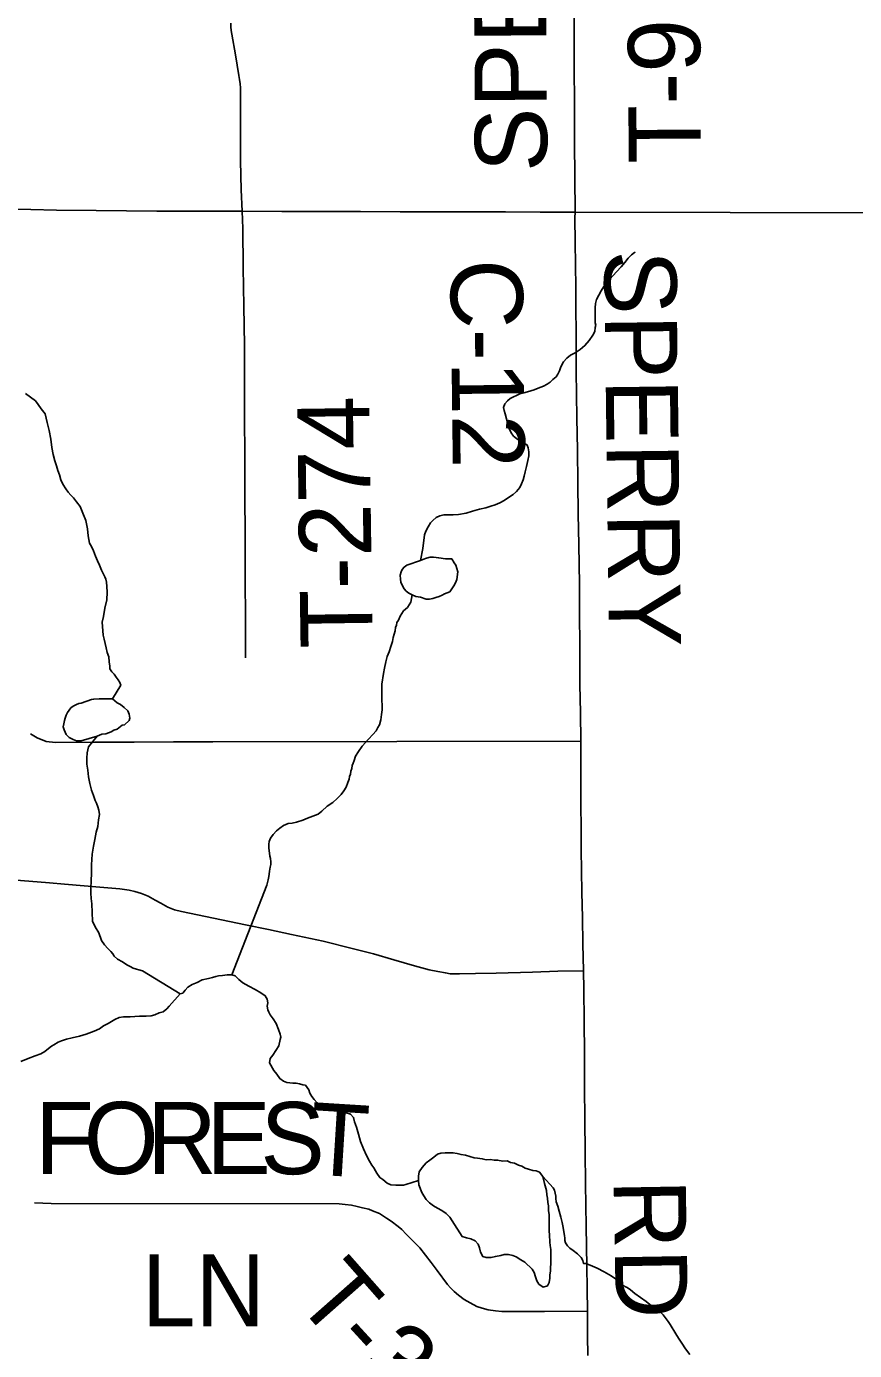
# Model space of a CAD drawing. Extents: x 103424 to 290657, y 38711 to 110967.
# Drawn here: x 112838 to 116302, y 74147 to 79687 of the extents above; entities that cross this region are included whole.
import ezdxf

# ---------------------------------------------------------------- set-up
doc = ezdxf.new("R2010")
doc.units = 0
for name, color, linetype in [('GM_X_County_Road', 7, 'Continuous'), ('GM_X_County_Road_Text', 7, 'Continuous'), ('GM_X_Minor_Lake', 7, 'Continuous'), ('GM_X_Minor_River', 7, 'Continuous'), ('GM_X_Township_Road', 7, 'Continuous'), ('GM_X_Township_Road_Text', 7, 'Continuous'), ('GM_X_US_Route', 7, 'Continuous'), ('SC_Scratch1', 7, 'Continuous')]:
    doc.layers.add(name, color=color, linetype=linetype)

msp = doc.modelspace()

# ---------------------------------------------------------------- linework, layer by layer
at = {"layer": 'GM_X_County_Road'}
for points in [[(115157.3, 76697.4), (115155.4, 76815.4), (115153.6, 76933.4), (115152.7, 77098.5), (115152.1, 77226), (115151.4, 77353.6), (115148.7, 77518.6), (115146.5, 77648.3), (115144.4, 77777.9), (115142.7, 77913.7), (115141.1, 78049.5), (115139.5, 78147.3), (115138, 78245.1), (115137.1, 78410.1), (115136.5, 78502.6), (115136, 78595.1), (115134.6, 78689.5), (115133.2, 78784), (115132.1, 78886), (115132.9, 78910)], [(115168.7, 75736), (115165.6, 75849.2), (115163.8, 75957.1), (115162, 76065.1), (115160.5, 76154.4), (115158.9, 76243.6), (115157.7, 76520.2), (115157, 76603.8), (115157.3, 76697.4)], [(115184.4, 74311.6), (115183.3, 74406.2), (115182.2, 74500.8), (115179.3, 74665.8), (115177.8, 74755.6), (115176.2, 74845.4), (115175.3, 74978.4), (115174.3, 75111.4), (115173.2, 75250.6), (115172.1, 75389.9), (115170.6, 75524.7), (115169.2, 75659.5), (115168.7, 75736)], [(115186.6, 74126.7), (115184.9, 74209.2), (115184.4, 74311.6)]]:
    msp.add_lwpolyline(points, dxfattribs=at)
at = {"layer": 'GM_X_Minor_Lake'}
for points in [[(114486.6, 77452.7), (114495.9, 77456.3), (114512, 77462.6), (114526.1, 77466.7), (114540.2, 77466.9), (114562.5, 77463.1), (114590.8, 77459.3), (114617.1, 77459.6), (114627.3, 77443.5), (114633.5, 77433.5), (114641.9, 77405.3), (114638.3, 77372.9), (114632.4, 77358.7), (114626.4, 77346.5), (114608.6, 77322.1), (114586.5, 77313.8), (114576.4, 77307.7), (114564.4, 77301.5), (114550.3, 77297.3), (114538.2, 77293.1), (114524.1, 77291), (114510, 77290.8), (114485.6, 77298.7), (114467.4, 77302.5), (114451.2, 77308.4), (114437, 77316.4), (114426.8, 77324.4), (114418.6, 77334.4), (114412.4, 77344.4), (114404.1, 77362.5), (114402, 77374.6), (114401.8, 77390.8), (114405.7, 77404.9), (114409.6, 77415.1), (114417.5, 77425.3), (114429.6, 77433.5), (114486.6, 77452.7)], [(114486.6, 77452.7), (114429.6, 77433.5), (114417.5, 77425.3), (114409.6, 77415.1), (114405.7, 77404.9), (114401.8, 77390.8), (114402, 77374.6), (114404.1, 77362.5), (114412.4, 77344.4), (114418.6, 77334.4), (114426.8, 77324.4), (114437, 77316.4), (114451.2, 77308.4), (114467.4, 77302.5), (114485.6, 77298.7), (114510, 77290.8), (114524.1, 77291), (114538.2, 77293.1), (114550.3, 77297.3)], [(114550.3, 77297.3), (114564.4, 77301.5), (114576.4, 77307.7), (114586.5, 77313.8), (114608.6, 77322.1), (114626.4, 77346.5), (114632.4, 77358.7), (114638.3, 77372.9), (114641.9, 77405.3), (114633.5, 77433.5), (114627.3, 77443.5), (114617.1, 77459.6), (114590.8, 77459.3), (114562.5, 77463.1), (114540.2, 77466.9), (114526.1, 77466.7), (114512, 77462.6), (114495.9, 77456.3), (114486.6, 77452.7)], [(113110, 76871), (113067, 76856.3), (113056.9, 76854.1), (113046.9, 76850), (113032.8, 76843.8), (113022.8, 76835.6), (113008.9, 76817.3), (113003, 76805.1), (112999.1, 76793), (112997.2, 76782.8), (112993.3, 76768.7), (112991.4, 76756.5), (112995.6, 76744.4), (113003.9, 76724.3), (113016.2, 76712.3), (113032.4, 76704.4), (113046.6, 76698.5), (113066.8, 76698.7), (113133.3, 76717.5), (113143.3, 76721.7), (113153.4, 76725.8), (113169.5, 76728), (113191.6, 76736.3), (113203.7, 76742.5), (113217.7, 76746.7), (113237.7, 76763), (113247.8, 76765.1), (113267.8, 76783.5), (113269.7, 76793.6), (113267.5, 76809.8), (113261.3, 76823.9), (113247, 76837.9), (113230.7, 76849.8), (113216.4, 76857.8), (113198.1, 76873.7), (113191.8, 76873.7)], [(113191.8, 76873.7), (113184, 76873.6), (113161.7, 76873.4), (113141.5, 76873.2), (113119.3, 76872.9), (113110, 76871)], [(114895.8, 74922.6), (114879.7, 74930.6), (114863.5, 74934.5), (114849.4, 74940.4), (114831.3, 74940.3), (114809.1, 74944.2), (114795.1, 74944.1), (114778.9, 74946), (114760.8, 74945.9), (114744.7, 74949.8), (114724.6, 74951.7), (114710.5, 74953.6), (114674.2, 74965.4), (114656, 74967.3), (114639.9, 74971.2), (114621.8, 74975.1), (114589.6, 74974.9), (114571.5, 74972.8), (114557.4, 74968.7), (114541.4, 74956.5), (114525.4, 74944.2), (114509.4, 74932), (114493.4, 74913.8), (114481.4, 74895.6), (114477.5, 74877.4), (114477.6, 74859.2), (114479.8, 74841.1), (114492.1, 74808.9), (114500.2, 74794.9), (114510.4, 74778.8), (114524.6, 74764.8), (114540.8, 74752.8), (114556.9, 74742.8), (114575.1, 74732.9), (114593.3, 74720.9), (114609.5, 74704.9), (114618.2, 74689.5)], [(115005.6, 74846.6), (114998.8, 74874.9), (114984.6, 74893), (114970.5, 74898.9), (114956.4, 74900.8), (114938.2, 74906.8), (114924.1, 74910.7), (114909.9, 74918.6), (114895.8, 74922.6)], [(114618.2, 74689.5), (114660.4, 74624.6), (114678.5, 74618.7), (114696.7, 74614.8), (114714.8, 74606.8), (114727, 74592.8), (114733.2, 74576.7), (114737.3, 74558.6), (114747.5, 74540.5), (114761.6, 74536.6), (114781.7, 74536.7), (114799.8, 74540.9), (114821.9, 74545.1), (114836, 74549.2), (114854.1, 74549.3), (114872.2, 74545.4), (114886.4, 74539.4), (114906.6, 74527.5), (114922.8, 74517.5), (114953.1, 74487.5), (114961.3, 74473.4), (114967.5, 74455.3), (114973.6, 74439.2), (114981.7, 74425.2), (114999.9, 74413.2), (115018, 74417.4), (115024, 74431.5), (115027.9, 74449.7), (115027.8, 74463.8), (115029.7, 74479.9), (115029.6, 74494.1), (115031.5, 74510.2), (115031.1, 74570.7), (115028.9, 74586.8), (115026.8, 74600.9), (115026.6, 74631.1), (115024.5, 74647.2), (115024, 74715.8), (115021.9, 74733.9), (115021.8, 74752.1), (115019.7, 74766.2), (115017.5, 74784.3), (115015.4, 74798.4), (115013.3, 74816.5), (115005.6, 74846.6)]]:
    msp.add_lwpolyline(points, dxfattribs=at)
at = {"layer": 'GM_X_Minor_River'}
for points in [[(114566.5, 77638.8), (114584.6, 77643.1), (114604.8, 77643.3), (114623, 77643.4), (114645.2, 77645.7), (114677.4, 77650.1), (114703.6, 77658.4), (114733.8, 77666.8), (114760, 77673.1), (114780.1, 77679.4), (114798.2, 77685.6), (114818.3, 77693.9), (114836.4, 77704.2), (114854.4, 77716.5), (114874.5, 77728.8), (114888.4, 77741), (114902.4, 77757.3), (114908.3, 77773.6), (114916.2, 77789.8), (114920, 77806), (114923.8, 77824.2), (114929.6, 77846.5), (114935.4, 77870.8), (114939.2, 77891), (114939, 77907.2), (114936.8, 77923.3), (114932.6, 77935.4), (114914.3, 77947.3), (114902.1, 77953.3), (114887.9, 77963.2), (114875.7, 77973.2), (114865.4, 77987.3), (114857.1, 78005.3), (114850.8, 78025.5), (114846.5, 78045.6), (114840.2, 78065.8), (114836, 78079.9), (114833.9, 78092), (114839.8, 78108.2), (114849.7, 78120.4), (114861.7, 78130.6), (114901.9, 78149.2), (114918, 78153.4), (114934.1, 78157.6), (114948.2, 78161.8), (114962.3, 78166), (114978.3, 78174.2), (115000.4, 78182.5), (115016.5, 78190.8), (115028.5, 78199), (115040.5, 78209.2), (115054.5, 78221.4), (115060.5, 78231.6), (115068.4, 78245.8), (115072.3, 78258), (115076.2, 78268.1), (115084.1, 78284.4), (115098.1, 78298.6), (115114.1, 78310.9), (115134.1, 78321.2), (115154.2, 78335.6), (115174.2, 78351.9), (115192.1, 78372.3), (115208, 78394.7), (115215.9, 78410.9), (115217.7, 78427.1), (115219.6, 78437.2), (115217.5, 78447.3), (115217.3, 78465.5), (115217.1, 78483.6), (115216.9, 78499.8), (115216.8, 78509.9), (115218.6, 78528.1), (115222.4, 78544.3), (115232.3, 78562.6), (115242.2, 78580.9), (115258.1, 78605.2), (115278, 78629.7), (115305.9, 78660.3), (115325.9, 78680.7), (115341.8, 78699), (115355.7, 78717.3), (115369.7, 78731.6), (115381.7, 78741.8), (115383.7, 78741.8), (115381.7, 78741.8)], [(113198.1, 76873.7), (113231.8, 76930.6), (113227.6, 76942.7), (113221.4, 76952.7), (113213.2, 76964.8), (113205, 76976.8), (113194.8, 76986.8), (113186.5, 76998.8), (113186.4, 77011), (113184.2, 77029.1), (113181.9, 77049.3), (113175.6, 77067.4), (113171.4, 77087.6), (113167.1, 77105.7), (113162.9, 77123.9), (113158.6, 77140), (113154, 77194.5), (113159.7, 77218.8), (113165.4, 77253.2), (113173.1, 77287.6), (113174.7, 77319.9), (113174.4, 77344.2), (113172.2, 77362.3), (113170.1, 77374.4), (113165.9, 77384.5), (113157.6, 77400.5), (113151.4, 77412.6), (113143.1, 77432.7), (113134.8, 77450.8), (113126.5, 77470.9), (113118.2, 77493.1), (113109.9, 77511.2), (113101.7, 77525.2), (113095.2, 77555.5), (113092.9, 77585.7), (113086.4, 77620), (113074, 77650.2), (113061.5, 77678.3), (113047.1, 77698.4), (113034.8, 77714.4), (113022.6, 77726.4), (113012.3, 77738.5), (113002.1, 77752.5), (112989.7, 77772.6), (112981.4, 77790.7), (112975.1, 77810.8), (112968.9, 77828.9), (112962.6, 77849), (112956.3, 77869.2), (112949.9, 77895.4), (112943.5, 77925.6), (112939.1, 77959.9), (112932.6, 77996.2), (112924.1, 78030.5), (112915.6, 78066.7), (112899.2, 78086.8), (112886.9, 78104.8), (112874.6, 78120.9), (112833.9, 78150.8)], [(114486.6, 77452.7), (114495.4, 77502.8), (114502.8, 77559.4), (114508.7, 77575.7), (114518.6, 77593.9), (114528.5, 77610.2), (114538.5, 77620.4), (114552.5, 77632.6), (114566.5, 77638.8)], [(113696.2, 75719.2), (113843.3, 76094.4), (113849.1, 76116.7), (113851, 76130.8), (113852.8, 76141), (113854.7, 76153.1), (113856.6, 76169.3), (113860.5, 76181.4), (113860.3, 76191.5), (113858.1, 76205.6), (113856, 76215.7), (113851.6, 76250), (113851.4, 76266.2), (113853.3, 76276.3), (113859.2, 76290.5), (113869.1, 76306.8), (113883.1, 76321), (113897.1, 76333.3), (113913.1, 76343.6), (113933.2, 76351.8), (113949.3, 76354), (113967.5, 76358.2), (113993.6, 76366.6), (114013.7, 76374.9), (114035.8, 76383.2), (114057.9, 76391.5), (114074, 76403.7), (114095.9, 76424.2), (114120, 76440.6), (114138, 76456.9), (114153.9, 76473.2), (114165.9, 76489.5), (114175.8, 76503.7), (114181.6, 76524), (114187.5, 76538.2), (114189.4, 76548.3), (114193.3, 76558.5), (114195.2, 76570.6), (114199.1, 76582.8), (114201, 76594.9), (114204.9, 76605), (114208.8, 76615.2), (114214.7, 76633.4), (114226.6, 76653.7), (114242.5, 76676.1), (114268.4, 76704.6), (114286.3, 76725), (114300.3, 76739.3), (114308.2, 76753.5), (114314.1, 76765.7), (114319.9, 76786), (114323.7, 76808.2), (114325.5, 76828.4), (114325.3, 76848.6), (114325.1, 76864.8), (114324.9, 76878.9), (114324.7, 76897.1), (114324.5, 76913.3), (114324.4, 76925.4), (114324.3, 76935.5), (114331.8, 76980), (114335.6, 77002.3), (114341.4, 77028.6), (114347.2, 77050.9), (114355, 77071.1), (114362.8, 77093.4), (114368.6, 77113.7), (114372.5, 77129.9), (114376.4, 77144.1), (114380.2, 77158.2), (114382.1, 77172.4), (114386, 77182.5), (114387.9, 77192.7), (114393.9, 77202.8), (114401.7, 77219.1), (114415.6, 77241.4), (114431.6, 77255.7), (114445.5, 77278.1), (114451.2, 77308.4)], [(113481, 75640.3), (113322.4, 75735.7), (113308.2, 75739.6), (113298.1, 75743.5), (113283.9, 75747.4), (113271.7, 75753.4), (113257.5, 75761.3), (113239.1, 75773.2), (113218.8, 75785.2), (113204.5, 75797.1), (113198.4, 75807.2), (113190.2, 75817.2), (113177.9, 75829.2), (113163.6, 75845.2), (113151.3, 75863.3), (113140.8, 75895.5), (113124.3, 75919.6), (113114, 75943.7), (113111.1, 76016.4), (113108.8, 76038.6), (113106.6, 76060.8), (113106.3, 76083), (113108, 76111.3), (113109.6, 76145.6), (113109.2, 76180), (113112.7, 76224.5), (113118.4, 76256.8), (113124.1, 76285.2), (113129.8, 76315.5), (113135.6, 76339.8), (113139.3, 76368.1), (113143.1, 76390.4), (113140.9, 76408.6), (113136.7, 76422.7), (113130.5, 76436.7), (113124.3, 76448.8), (113118, 76468.9), (113109.6, 76491.1), (113103.2, 76519.3), (113096.9, 76547.5), (113094.5, 76575.8), (113090.2, 76600), (113089.9, 76626.2), (113091.7, 76648.4), (113097.4, 76672.7), (113133.3, 76717.5)], [(113225.7, 75540.8), (113243.8, 75543), (113258, 75543.1), (113272.1, 75543.3), (113290.3, 75545.5), (113310.5, 75545.7), (113338.7, 75546), (113358.9, 75548.2), (113375, 75552.4), (113393.1, 75560.7), (113409.2, 75564.9), (113425.2, 75577.1), (113435.2, 75587.4), (113481, 75640.3), (113491.1, 75642.4), (113501, 75654.7), (113513, 75666.9), (113531.1, 75679.2), (113551.2, 75687.5), (113573.3, 75697.8), (113599.4, 75704.1), (113615.5, 75708.3), (113629.6, 75712.5), (113641.7, 75714.7), (113657.8, 75716.8), (113678, 75719.1), (113696.2, 75719.2), (113710.4, 75715.3), (113726.7, 75699.3), (113743, 75685.4), (113767.4, 75671.5), (113793.8, 75657.6), (113818.2, 75643.7), (113836.5, 75631.8), (113844.8, 75617.7), (113847, 75601.6), (113845.1, 75587.4), (113847.3, 75573.3), (113851.5, 75563.2), (113857.7, 75551.2), (113870, 75535.1), (113882.3, 75515.1), (113892.7, 75490.9), (113899, 75470.8), (113901.2, 75458.7), (113899.3, 75448.6), (113893.5, 75422.3), (113867.7, 75383.6), (113857.8, 75369.4), (113854, 75351.1), (113872.5, 75319), (113884.8, 75303), (113897.1, 75284.9), (113913.4, 75275), (113927.6, 75269.1), (113939.7, 75267.2), (113951.9, 75265.3), (113966, 75265.4), (113980.2, 75263.5), (113994.4, 75259.6), (114004.5, 75257.7), (114018.8, 75237.7), (114023, 75223.6), (114031.3, 75209.5), (114041.5, 75197.5), (114053.8, 75183.5), (114072.1, 75171.5), (114094.5, 75161.7), (114120.8, 75155.9), (114151.1, 75150.1), (114175.5, 75142.3), (114193.7, 75136.4), (114206, 75122.4), (114210.2, 75104.2), (114218.6, 75082.1), (114227, 75051.9), (114235.4, 75021.7), (114247.9, 74991.5), (114260.3, 74963.3), (114272.7, 74939.2), (114283, 74923.2), (114291.2, 74911.1), (114297.4, 74899.1), (114303.6, 74889), (114315.9, 74871), (114328.1, 74863), (114346.5, 74847), (114362.7, 74841.1), (114382.9, 74839.3), (114401.1, 74839.5), (114415.2, 74839.6), (114425.3, 74841.8), (114477.6, 74859.2)], [(112813.8, 75356.9), (112844, 75369.3), (112874.1, 75379.7), (112898.3, 75388.1), (112914.3, 75398.3), (112930.3, 75410.6), (112942.3, 75420.8), (112952.4, 75427), (112970.4, 75437.3), (112984.5, 75443.5), (113004.6, 75449.7), (113028.8, 75456), (113059, 75462.4), (113087.2, 75470.8), (113121.3, 75483.2), (113143.4, 75493.5), (113159.5, 75505.8), (113179.5, 75516.1), (113193.6, 75524.3), (113207.6, 75532.6), (113225.7, 75540.8)], [(115612.9, 74130.5), (115594.5, 74154.5), (115580.1, 74178.6), (115565.7, 74198.7), (115555.4, 74216.8), (115530.7, 74256.9), (115522.5, 74268.9), (115510.2, 74285), (115502, 74297), (115489.7, 74309), (115473.4, 74321), (115453, 74334.9), (115430.6, 74352.9), (115406.2, 74368.8), (115383.8, 74386.7), (115365.5, 74400.7), (115351.2, 74410.6), (115341.1, 74414.6), (115328.8, 74426.6), (115306.4, 74444.5), (115284, 74460.5), (115255.5, 74476.4), (115225, 74492.2), (115196.6, 74504), (115178.4, 74511.9), (115168.3, 74511.8), (115166.1, 74523.9), (115157.9, 74536), (115143.6, 74552), (115125.2, 74566), (115111, 74575.9), (115100.8, 74585.9), (115092.5, 74597.9), (115090.4, 74608), (115090.3, 74618.1), (115088.2, 74628.2), (115086, 74644.3), (115083.7, 74662.5), (115079.5, 74682.7), (115073.1, 74704.8), (115066.8, 74731), (115060.5, 74751.1), (115054.2, 74769.3), (115052, 74783.4), (115051.9, 74793.5), (115047.6, 74817.7), (115041.4, 74827.7), (114998.8, 74874.9)]]:
    msp.add_lwpolyline(points, dxfattribs=at)
at = {"layer": 'GM_X_Township_Road'}
for points in [[(115132.9, 78910), (115132.1, 79056.1), (115131.2, 79202.2), (115130.5, 79367.3), (115129.8, 79512.3), (115129, 79657.3), (115128.5, 79822.4)], [(113740.5, 78913.6), (113735.5, 79003), (113732.8, 79124.2), (113733.2, 79268.2), (113733.6, 79412.2), (113733.1, 79429.6), (113731.8, 79447), (113729.5, 79464.4), (113726.8, 79481.6), (113711.9, 79568.2), (113696.9, 79654.7), (113694.7, 79669.8), (113692.9, 79684.9), (113692.1, 79700.1)], [(113754, 77044.8), (113753.4, 77209.8), (113752.8, 77374.9), (113752.1, 77559), (113751.5, 77724.1), (113750.9, 77889.2), (113750.3, 78054.2), (113749.8, 78203.1), (113749.2, 78351.9), (113747, 78517), (113744.9, 78679), (113742.8, 78840.9), (113740.5, 78913.6)], [(115157.3, 76697.4), (115155.4, 76815.4), (115153.6, 76933.4), (115152.7, 77098.5), (115152.1, 77226), (115151.4, 77353.6), (115148.7, 77518.6), (115146.5, 77648.3), (115144.4, 77777.9), (115142.7, 77913.7), (115141.1, 78049.5), (115139.5, 78147.3), (115138, 78245.1), (115137.1, 78410.1), (115136.5, 78502.6), (115136, 78595.1), (115134.6, 78689.5), (115133.2, 78784), (115132.1, 78886), (115132.9, 78910)], [(112854.8, 76727.7), (112882.5, 76711.1), (112920.6, 76695.6), (112958.3, 76691.2), (113123.4, 76692), (113288.4, 76692.9), (113453.2, 76693.7), (113618, 76694.6), (115157.3, 76697.4)], [(115168.7, 75736), (115165.6, 75849.2), (115163.8, 75957.1), (115162, 76065.1), (115160.5, 76154.4), (115158.9, 76243.6), (115157.7, 76520.2), (115157, 76603.8), (115157.3, 76697.4)], [(112778.2, 76116.3), (112934.5, 76104.2), (112996, 76098.1), (113078.8, 76091.4), (113161.5, 76084.8), (113228.4, 76079), (113267, 76073.3), (113290.4, 76067.8), (113318.8, 76059.4), (113346.1, 76047.8), (113375.4, 76032.1), (113399.6, 76018.4), (113429.7, 76002.7), (113457.2, 75991.6), (113486.6, 75984.4), (113620, 75956.6), (113753.4, 75928.8), (113849.7, 75908.6), (113945.9, 75888.3), (114078.6, 75860.4), (114200.2, 75829.6), (114289, 75806.8), (114375, 75782.1), (114461, 75757.4), (114522.8, 75740.1), (114559.1, 75732.9), (114590.6, 75727.1), (114609.9, 75724), (114648.9, 75722.7), (114716.2, 75724.7), (114802.4, 75725.5), (114955.3, 75730.8), (115060.5, 75734), (115168.7, 75736)], [(115184.4, 74311.6), (115183.3, 74406.2), (115182.2, 74500.8), (115179.3, 74665.8), (115177.8, 74755.6), (115176.2, 74845.4), (115175.3, 74978.4), (115174.3, 75111.4), (115173.2, 75250.6), (115172.1, 75389.9), (115170.6, 75524.7), (115169.2, 75659.5), (115168.7, 75736)], [(112870.6, 74765.9), (112940.8, 74763), (114145.6, 74760.8), (114170.6, 74758.7), (114197.1, 74755.3), (114220.9, 74750.1), (114244.1, 74743.9), (114270.3, 74738.2), (114285.8, 74731.5), (114314.6, 74720), (114344.6, 74700.5), (114364.2, 74689.1), (114392.3, 74665.7), (114408.8, 74654.2), (114426.8, 74634.5), (114445.9, 74615.4), (114484.1, 74576.6), (114531.2, 74515.1), (114555.6, 74482), (114599.9, 74424.3), (114612.3, 74409.7), (114626.8, 74395), (114644.7, 74379.5), (114668.5, 74361.4), (114694.3, 74346.3), (114721.7, 74332.3), (114744.6, 74324.4), (114770.1, 74318.2), (114800.3, 74313.9), (114826.8, 74311.3), (114857.5, 74310.6), (114910.7, 74310.1), (115004.6, 74311.3), (115184.4, 74311.6)], [(115186.6, 74126.7), (115184.9, 74209.2), (115184.4, 74311.6)]]:
    msp.add_lwpolyline(points, dxfattribs=at)
at = {"layer": 'GM_X_US_Route'}
for points in [[(112746.7, 78923), (112855.1, 78920.9), (112963.5, 78918.7), (113128.6, 78917), (113256.1, 78915.7), (113383.5, 78914.4), (113548.6, 78914.1), (113740.5, 78913.6), (113905.5, 78913.1), (114070.6, 78912.7), (114235.7, 78912.3), (114400.7, 78911.8), (114565.8, 78911.4), (114842.5, 78910.7), (114987.7, 78910.4), (115132.9, 78910)], [(115132.9, 78910), (116430.7, 78907.5)]]:
    msp.add_lwpolyline(points, dxfattribs=at)
at = {"layer": 'SC_Scratch1'}
for points in [[(112746.7, 78923), (112855.1, 78920.9), (112963.5, 78918.7), (113128.6, 78917), (113256.1, 78915.7), (113383.5, 78914.4), (113548.6, 78914.1), (113740.5, 78913.6), (113905.5, 78913.1), (114070.6, 78912.7), (114235.7, 78912.3), (114400.7, 78911.8), (114565.8, 78911.4), (114842.5, 78910.7), (114987.7, 78910.4), (115132.9, 78910)], [(115132.9, 78910), (116430.7, 78907.5)]]:
    msp.add_lwpolyline(points, dxfattribs=at)

# ---------------------------------------------------------------- texts
at = {"layer": 'GM_X_County_Road_Text'}
for s, rotation, p in [('SPERRY', 270.7248, (115254.3, 78748.9)), ('C-12', 270.6914, (114611.1, 78711.9)), ('RD', 270.9872, (115294.1, 74862))]:
    msp.add_text(s, height=301.87, rotation=rotation, dxfattribs=at).set_placement(p)
at = {"layer": 'GM_X_Township_Road_Text'}
for s, height, rotation, p in [('SPERRY', 301.87, 90.3643, (115016.8, 79078.3)), ('T-90', 301.87, 90.3535, (115659.5, 79113.5)), ('T-274', 301.87, 90.8216, (114286.5, 77087.6)), ('F', 301.9, 0, (112873.2, 74885.7)), ('O', 301.9, 0, (113076.8, 74885.7)), ('R', 301.9, 0, (113342.5, 74885.7)), ('E', 301.9, 359.9957, (113590.4, 74885.7)), ('S', 301.9, 359.8147, (113816, 74885.7)), ('T', 301.9, 356.4234, (114014.9, 74885.2)), ('LN', 301.87, 0, (113320.3, 74248)), ('T', 301.9, 311.4097, (113954, 74359)), ('-', 301.9, 312.4711, (114107.4, 74185.1)), ('3', 301.9, 318.7402, (114216.9, 74068.5))]:
    msp.add_text(s, height=height, rotation=rotation, dxfattribs=at).set_placement(p)

doc.saveas('drawing.dxf')
